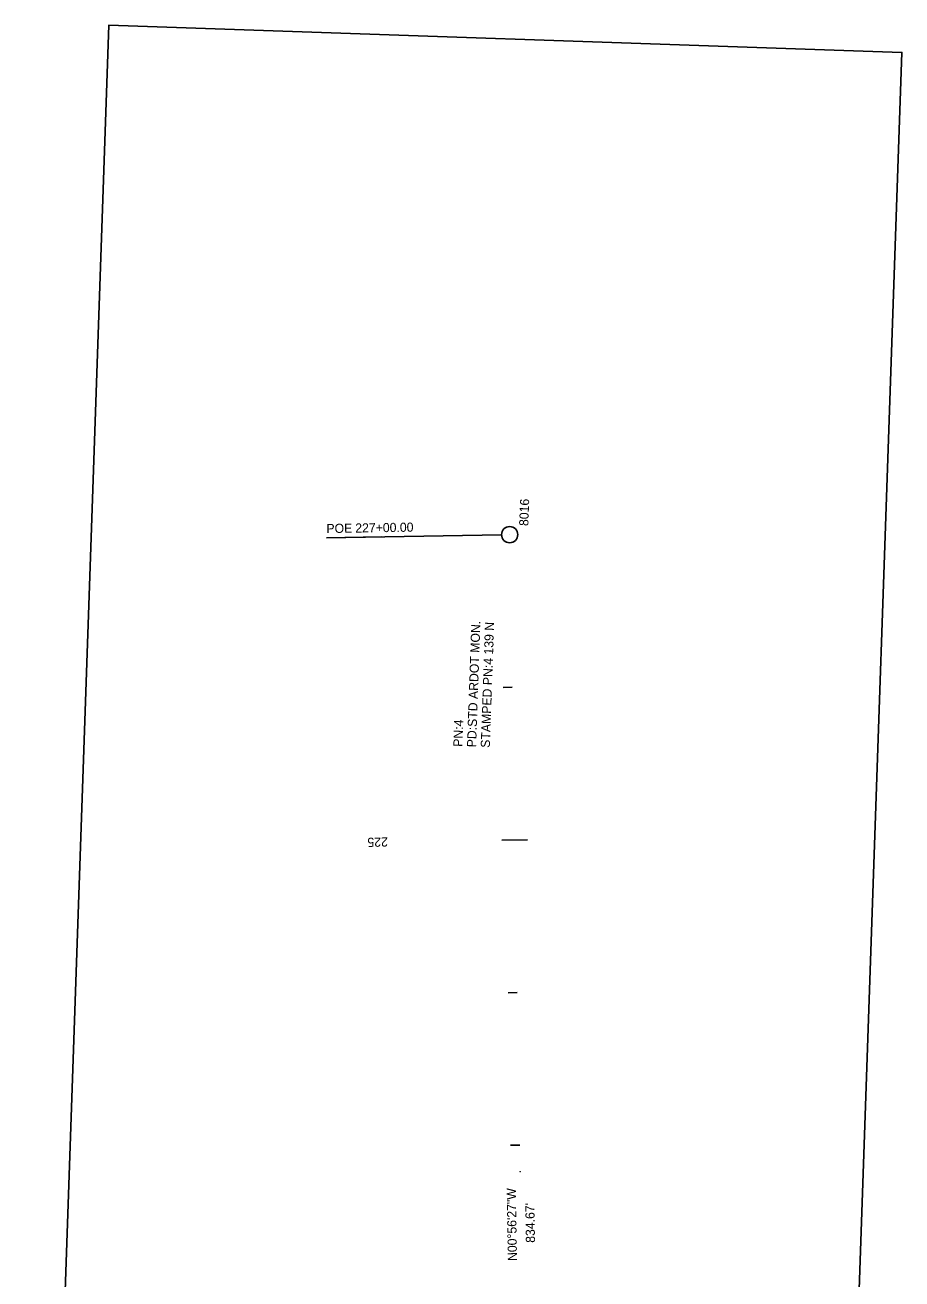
# Model space of a CAD drawing. Extents: x 1802363 to 1804577, y 572235 to 575339.
# Drawn here: x 1803203 to 1803778, y 574517 to 575339 of the extents above; entities that cross this region are included whole.
import ezdxf

# ---------------------------------------------------------------- set-up
doc = ezdxf.new("R2010")
doc.units = 0
for name, color, linetype in [('_CIVIL_CONSTRUCTION', 7, 'Continuous'), ('DSN_DRFT_Named-Boundary', 7, 'Continuous'), ('DSN_RDWY_Alignment Annotation', 7, 'Continuous'), ('DSN_ROW_Point-Annotation', 7, 'Continuous'), ('S_PRIMARY_CTL_ANNOT', 7, 'Continuous')]:
    doc.layers.add(name, color=color, linetype=linetype)

msp = doc.modelspace()

# ---------------------------------------------------------------- linework, layer by layer
at = {"layer": '_CIVIL_CONSTRUCTION'}
msp.add_circle((1803527.31, 574587.6), 0.05, dxfattribs=at)
at = {"layer": 'DSN_DRFT_Named-Boundary'}
msp.add_lwpolyline([(1803202.89, 573749.55), (1803722.58, 573731.59), (1803777.51, 575320.76), (1803257.82, 575338.72)], close=True, dxfattribs=at)
at = {"layer": 'DSN_RDWY_Alignment Annotation'}
for p, q in [((1803515.11, 575004.79), (1803400.47, 575002.9)), ((1803400.47, 575002.9), (1803436.47, 575003.5)), ((1803520.45, 575004.88), (1803520.45, 575004.88)), ((1803516.1, 574904.79), (1803522.1, 574904.89)), ((1803515.34, 574804.76), (1803532.14, 574805.04)), ((1803519.38, 574704.82), (1803525.38, 574704.92)), ((1803521.02, 574604.83), (1803527.02, 574604.93))]:
    msp.add_line(p, q, dxfattribs=at)
msp.add_circle((1803520.45, 575004.88), 5.34, dxfattribs=at)

# ---------------------------------------------------------------- texts
for s, rotation, p in [('8016', 88.02045, (1803532.65, 575010.46)), ('POE ', 0.94083, (1803400.42, 575005.9)), ('227+00.00', 0.94083, (1803419.32, 575006.21)), ('225', 180.94083, (1803440.59, 574806.54)), ('N00°56\'27"W', 90.94083, (1803525.27, 574529.09))]:
    msp.add_text(s, height=6, rotation=rotation, dxfattribs=at).set_placement(p)
at = {"layer": 'DSN_ROW_Point-Annotation'}
msp.add_text("834.67'", height=6, rotation=90.94083, dxfattribs=at).set_placement((1803537.07, 574541))
at = {"layer": 'S_PRIMARY_CTL_ANNOT'}
for s, p in [('PD:STD ARDOT MON.', (1803498.47, 574865.49)), ('STAMPED PN:4 139 N', (1803507.47, 574865.18)), ('PN:4', (1803489.48, 574865.8))]:
    msp.add_text(s, height=6, rotation=88.02045, dxfattribs=at).set_placement(p)

doc.saveas('drawing.dxf')
